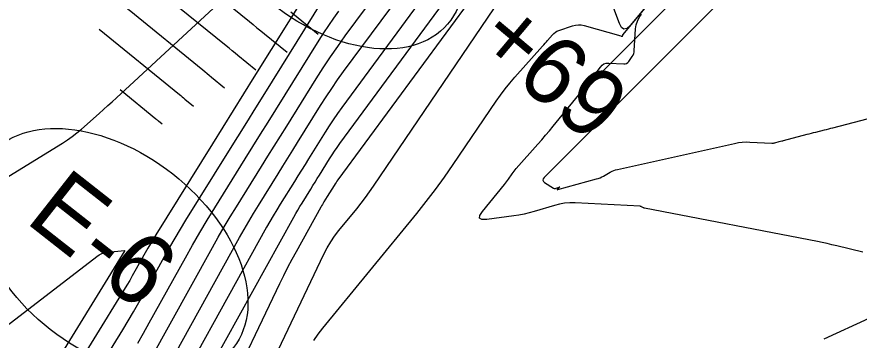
# Model space of a CAD drawing. Extents: x 1005228 to 1008882, y 1883389 to 1885754.
# Drawn here: x 1007871.4 to 1007945.8, y 1884571 to 1884599.6 of the extents above; entities that cross this region are included whole.
import ezdxf

# ---------------------------------------------------------------- set-up
doc = ezdxf.new("R2010")
doc.units = 0
for name, color, linetype in [('ATDIMS', 7, 'Continuous'), ('C-ANNO-NOTE', 7, 'Continuous'), ('R_Erosion', 7, 'Continuous'), ('S_BASELINE', 7, 'Continuous'), ('S_BRIDGE', 7, 'Continuous'), ('TSOBSTACLE', 7, 'Continuous')]:
    doc.layers.add(name, color=color, linetype=linetype)

msp = doc.modelspace()

# ---------------------------------------------------------------- linework, layer by layer
at = {"layer": 'ATDIMS'}
for points in [[(1007923.1, 1884594.77), (1007942.567, 1884614.269)], [(1007886.556, 1884603.544), (1007891.911, 1884599.18), (1007892.244, 1884598.909), (1007892.576, 1884598.638), (1007892.908, 1884598.366), (1007893.239, 1884598.094), (1007895.228, 1884596.461)], [(1007942.665, 1884571.126), (1007950.616, 1884574.78)]]:
    msp.add_lwpolyline(points, dxfattribs=at)
at = {"layer": 'C-ANNO-NOTE'}
for points in [[(1007897.6, 1884570.983), (1007897.982, 1884571.546), (1007898.398, 1884572.087), (1007906.686, 1884582.209), (1007907.529, 1884583.263), (1007908.348, 1884584.336), (1007909.143, 1884585.427), (1007909.912, 1884586.536), (1007913.704, 1884592.136), (1007914.089, 1884592.685), (1007914.492, 1884593.22), (1007914.912, 1884593.742), (1007915.349, 1884594.25), (1007917.803, 1884597.007), (1007917.915, 1884597.132), (1007918.026, 1884597.258), (1007918.136, 1884597.384), (1007918.247, 1884597.511), (1007918.688, 1884598.018), (1007918.804, 1884598.135), (1007918.933, 1884598.235), (1007919.073, 1884598.316), (1007919.226, 1884598.38), (1007920.449, 1884598.797), (1007920.706, 1884598.864), (1007920.965, 1884598.891), (1007921.224, 1884598.878), (1007921.484, 1884598.824), (1007924.723, 1884597.905), (1007924.736, 1884597.901), (1007924.75, 1884597.899), (1007924.764, 1884597.897), (1007924.777, 1884597.896), (1007924.852, 1884597.891), (1007924.856, 1884597.892), (1007924.859, 1884597.893), (1007924.862, 1884597.895), (1007924.864, 1884597.897), (1007924.873, 1884597.909), (1007924.874, 1884597.912), (1007924.876, 1884597.916), (1007924.877, 1884597.919), (1007924.877, 1884597.923), (1007924.88, 1884597.974), (1007924.882, 1884597.984), (1007924.885, 1884597.993), (1007924.889, 1884598.001), (1007924.894, 1884598.009), (1007935.103, 1884610.258)], [(1007932.763, 1884607.494), (1007925.54, 1884598.831), (1007925.248, 1884598.563), (1007924.992, 1884598.501), (1007924.771, 1884598.645), (1007924.586, 1884598.997), (1007923.92, 1884600.817)], [(1007898.566, 1884604.321), (1007892.309, 1884594.267), (1007891.393, 1884592.794), (1007890.477, 1884591.322), (1007889.56, 1884589.85), (1007888.644, 1884588.377), (1007883.639, 1884580.334), (1007883.396, 1884579.937), (1007883.157, 1884579.538), (1007882.924, 1884579.135), (1007882.696, 1884578.729), (1007881.793, 1884577.1), (1007881.565, 1884576.694), (1007881.333, 1884576.291), (1007881.095, 1884575.89), (1007880.854, 1884575.492), (1007875.485, 1884566.77)], [(1007883.122, 1884569.228), (1007888.645, 1884579.198), (1007889.159, 1884580.112), (1007889.685, 1884581.019), (1007890.222, 1884581.919), (1007890.77, 1884582.813), (1007892.987, 1884586.375), (1007893.541, 1884587.266), (1007894.095, 1884588.156), (1007894.649, 1884589.047), (1007895.203, 1884589.937), (1007897.808, 1884594.123), (1007898.423, 1884595.091), (1007899.056, 1884596.046), (1007899.708, 1884596.988), (1007900.377, 1884597.919), (1007903.091, 1884601.616)], [(1007883.188, 1884565.925), (1007891.038, 1884580.093), (1007891.44, 1884580.808), (1007891.851, 1884581.518), (1007892.271, 1884582.223), (1007892.7, 1884582.922), (1007894.434, 1884585.708), (1007894.868, 1884586.404), (1007895.301, 1884587.101), (1007895.735, 1884587.798), (1007896.168, 1884588.494), (1007898.19, 1884591.744), (1007898.679, 1884592.513), (1007899.182, 1884593.272), (1007899.7, 1884594.021), (1007900.232, 1884594.761), (1007905.153, 1884601.463)], [(1007907.314, 1884601.446), (1007900.065, 1884591.573), (1007899.681, 1884591.039), (1007899.308, 1884590.498), (1007898.945, 1884589.951), (1007898.592, 1884589.396), (1007897.133, 1884587.051), (1007896.82, 1884586.548), (1007896.507, 1884586.046), (1007896.195, 1884585.543), (1007895.882, 1884585.041), (1007894.631, 1884583.03), (1007894.321, 1884582.526), (1007894.018, 1884582.017), (1007893.722, 1884581.505), (1007893.431, 1884580.989), (1007883.254, 1884562.621)], [(1007888.575, 1884568.802), (1007895.824, 1884581.885), (1007896.003, 1884582.202), (1007896.185, 1884582.517), (1007896.371, 1884582.829), (1007896.561, 1884583.139), (1007897.329, 1884584.373), (1007897.521, 1884584.682), (1007897.713, 1884584.99), (1007897.905, 1884585.299), (1007898.098, 1884585.608), (1007898.994, 1884587.048), (1007899.21, 1884587.389), (1007899.433, 1884587.725), (1007899.663, 1884588.057), (1007899.899, 1884588.385), (1007909.476, 1884601.429)], [(1007869.094, 1884584.562), (1007875.398, 1884588.427), (1007875.836, 1884588.709), (1007876.259, 1884589.009), (1007876.67, 1884589.328), (1007877.066, 1884589.665), (1007878.625, 1884591.049), (1007879.013, 1884591.397), (1007879.4, 1884591.746), (1007879.786, 1884592.096), (1007880.17, 1884592.449), (1007889.129, 1884600.717)], [(1007876.933, 1884565.765), (1007880.724, 1884571.923), (1007881.208, 1884572.72), (1007881.683, 1884573.523), (1007882.149, 1884574.331), (1007882.606, 1884575.144), (1007884.414, 1884578.408), (1007884.872, 1884579.221), (1007885.339, 1884580.028), (1007885.817, 1884580.829), (1007886.304, 1884581.624), (1007890.092, 1884587.71), (1007890.887, 1884588.988), (1007891.683, 1884590.267), (1007892.478, 1884591.545), (1007893.274, 1884592.824), (1007898.313, 1884600.921)], [(1007893.585, 1884568.341), (1007898.488, 1884578.626), (1007898.772, 1884579.177), (1007899.086, 1884579.708), (1007899.433, 1884580.22), (1007899.811, 1884580.711), (1007901.387, 1884582.635), (1007901.775, 1884583.121), (1007902.152, 1884583.614), (1007902.518, 1884584.117), (1007902.872, 1884584.627), (1007913.557, 1884600.406)], [(1007946.076, 1884578.803), (1007943.789, 1884579.353), (1007943.361, 1884579.453), (1007942.933, 1884579.549), (1007942.503, 1884579.64), (1007942.073, 1884579.726), (1007926.805, 1884582.689), (1007926.77, 1884582.697), (1007926.736, 1884582.708), (1007926.704, 1884582.722), (1007926.672, 1884582.738), (1007926.547, 1884582.808), (1007926.515, 1884582.824), (1007926.482, 1884582.836), (1007926.448, 1884582.843), (1007926.412, 1884582.847), (1007920.673, 1884583.147), (1007920.21, 1884583.151), (1007919.752, 1884583.116), (1007919.299, 1884583.042), (1007918.85, 1884582.927), (1007917.066, 1884582.392), (1007916.618, 1884582.267), (1007916.166, 1884582.161), (1007915.71, 1884582.072), (1007915.25, 1884582.001), (1007912.881, 1884581.684), (1007912.445, 1884581.673), (1007912.234, 1884581.788), (1007912.247, 1884582.028), (1007912.485, 1884582.394), (1007914.435, 1884584.774), (1007914.526, 1884584.889), (1007914.615, 1884585.005), (1007914.701, 1884585.123), (1007914.784, 1884585.243), (1007915.112, 1884585.728), (1007915.196, 1884585.848), (1007915.284, 1884585.964), (1007915.376, 1884586.078), (1007915.471, 1884586.189), (1007917.379, 1884588.333), (1007917.728, 1884588.728), (1007918.072, 1884589.127), (1007918.413, 1884589.529), (1007918.749, 1884589.935), (1007921.806, 1884593.659), (1007921.952, 1884593.839), (1007922.095, 1884594.023), (1007922.234, 1884594.208), (1007922.37, 1884594.397), (1007922.908, 1884595.155), (1007923.055, 1884595.319), (1007923.226, 1884595.433), (1007923.422, 1884595.496), (1007923.642, 1884595.508), (1007924.979, 1884595.436), (1007925.109, 1884595.444), (1007925.225, 1884595.482), (1007925.326, 1884595.55), (1007925.413, 1884595.648), (1007925.728, 1884596.102), (1007925.798, 1884596.218), (1007925.851, 1884596.341), (1007925.886, 1884596.47), (1007925.903, 1884596.604), (1007926.024, 1884598.522), (1007926.074, 1884598.878), (1007926.176, 1884599.212), (1007926.332, 1884599.525), (1007926.54, 1884599.817)], [(1007865.877, 1884568.776), (1007878.42, 1884578.419), (1007878.633, 1884578.561), (1007878.859, 1884578.67), (1007879.098, 1884578.746), (1007879.35, 1884578.789), (1007880.9, 1884578.948), (1007880.904, 1884578.948), (1007880.909, 1884578.945), (1007880.91, 1884578.944), (1007880.91, 1884578.942), (1007874.036, 1884567.776)]]:
    msp.add_lwpolyline(points, dxfattribs=at)
at = {"layer": 'R_Erosion'}
for centre, major_axis in [((1007899.028, 1884607.879), (10.39, -8.925)), ((1007879.729, 1884578.828), (10.768, -8.465))]:
    msp.add_ellipse(centre, major_axis=major_axis, ratio=0.638788, dxfattribs=at)
at = {"layer": 'S_BRIDGE'}
for points in [[(1007911.637, 1884601.413), (1007899.732, 1884585.197), (1007899.644, 1884585.075), (1007899.559, 1884584.951), (1007899.476, 1884584.826), (1007899.395, 1884584.7), (1007898.991, 1884584.05), (1007898.777, 1884583.706), (1007898.491, 1884583.247), (1007898.421, 1884583.132), (1007898.351, 1884583.016), (1007898.284, 1884582.899), (1007898.218, 1884582.781), (1007896.03, 1884578.833), (1007895.649, 1884578.132), (1007895.279, 1884577.427), (1007894.919, 1884576.715), (1007894.571, 1884575.998), (1007889.65, 1884565.676)], [(1007882.042, 1884570.751), (1007882.554, 1884571.638), (1007883.056, 1884572.532), (1007886.252, 1884578.302), (1007886.878, 1884579.415), (1007887.518, 1884580.52), (1007888.172, 1884581.616), (1007888.84, 1884582.705), (1007891.539, 1884587.043), (1007892.214, 1884588.127), (1007892.889, 1884589.212), (1007893.564, 1884590.296), (1007894.239, 1884591.38), (1007898.061, 1884597.522), (1007898.48, 1884598.181), (1007898.911, 1884598.832), (1007899.355, 1884599.475), (1007899.811, 1884600.109)]]:
    msp.add_lwpolyline(points, dxfattribs=at)
at = {"layer": 'TSOBSTACLE'}
for points in [[(1007946.48, 1884613.972), (1007917.936, 1884585.382), (1007917.847, 1884585.262), (1007917.825, 1884585.15), (1007917.872, 1884585.045), (1007917.986, 1884584.949), (1007918.767, 1884584.462), (1007918.822, 1884584.435), (1007918.879, 1884584.422), (1007918.937, 1884584.424), (1007918.997, 1884584.441), (1007919.256, 1884584.543), (1007919.296, 1884584.556), (1007919.312, 1884584.555), (1007919.306, 1884584.54), (1007919.276, 1884584.511), (1007919.112, 1884584.366), (1007919.083, 1884584.336), (1007919.078, 1884584.318), (1007919.095, 1884584.314), (1007919.136, 1884584.322), (1007922.563, 1884585.263), (1007922.726, 1884585.313), (1007922.885, 1884585.374), (1007923.04, 1884585.444), (1007923.191, 1884585.524), (1007923.787, 1884585.865), (1007923.938, 1884585.944), (1007924.094, 1884586.012), (1007924.255, 1884586.067), (1007924.42, 1884586.11), (1007934.758, 1884588.412), (1007935.096, 1884588.476), (1007935.437, 1884588.517), (1007935.779, 1884588.535), (1007936.123, 1884588.53), (1007938.05, 1884588.439), (1007938.121, 1884588.438), (1007938.192, 1884588.443), (1007938.261, 1884588.453), (1007938.33, 1884588.468), (1007938.71, 1884588.568), (1007938.81, 1884588.594), (1007938.943, 1884588.629), (1007939.009, 1884588.646), (1007939.075, 1884588.664), (1007941.17, 1884589.217), (1007941.359, 1884589.267), (1007941.549, 1884589.316), (1007941.74, 1884589.365), (1007941.93, 1884589.413), (1007942.691, 1884589.603), (1007942.882, 1884589.651), (1007943.072, 1884589.699), (1007943.262, 1884589.748), (1007943.452, 1884589.797), (1007948.4, 1884591.092)], [(1007889.719, 1884593.293), (1007888.558, 1884594.246), (1007888.365, 1884594.405), (1007888.171, 1884594.563), (1007887.977, 1884594.722), (1007887.783, 1884594.88), (1007881.281, 1884600.178), (1007881.236, 1884600.215), (1007881.191, 1884600.252), (1007881.146, 1884600.289), (1007881.101, 1884600.326), (1007880.921, 1884600.475), (1007880.876, 1884600.512), (1007880.831, 1884600.549), (1007880.786, 1884600.586), (1007880.74, 1884600.623), (1007874.838, 1884605.434)], [(1007892.473, 1884594.877), (1007890.899, 1884596.17), (1007890.636, 1884596.385), (1007890.373, 1884596.601), (1007890.11, 1884596.816), (1007889.847, 1884597.03), (1007883.919, 1884601.861)], [(1007897.982, 1884598.045), (1007895.58, 1884600.018)], [(1007878.625, 1884598.511), (1007878.644, 1884598.495), (1007885.719, 1884592.73), (1007885.844, 1884592.628), (1007885.969, 1884592.526), (1007886.093, 1884592.424), (1007886.218, 1884592.322), (1007886.965, 1884591.708)], [(1007880.491, 1884593.158), (1007883.655, 1884590.58), (1007883.71, 1884590.535), (1007883.766, 1884590.489), (1007883.822, 1884590.443), (1007883.877, 1884590.398), (1007884.211, 1884590.124)]]:
    msp.add_lwpolyline(points, dxfattribs=at)

# ---------------------------------------------------------------- texts
at = {"layer": 'R_Erosion'}
msp.add_text('E-6', height=6.2498, rotation=321.82832, dxfattribs=at).set_placement((1007871.984, 1884581.527))
at = {"layer": 'S_BASELINE'}
msp.add_text('+69', height=6, rotation=319.99998, dxfattribs=at).set_placement((1007911.622, 1884597.026))

doc.saveas('drawing.dxf')
